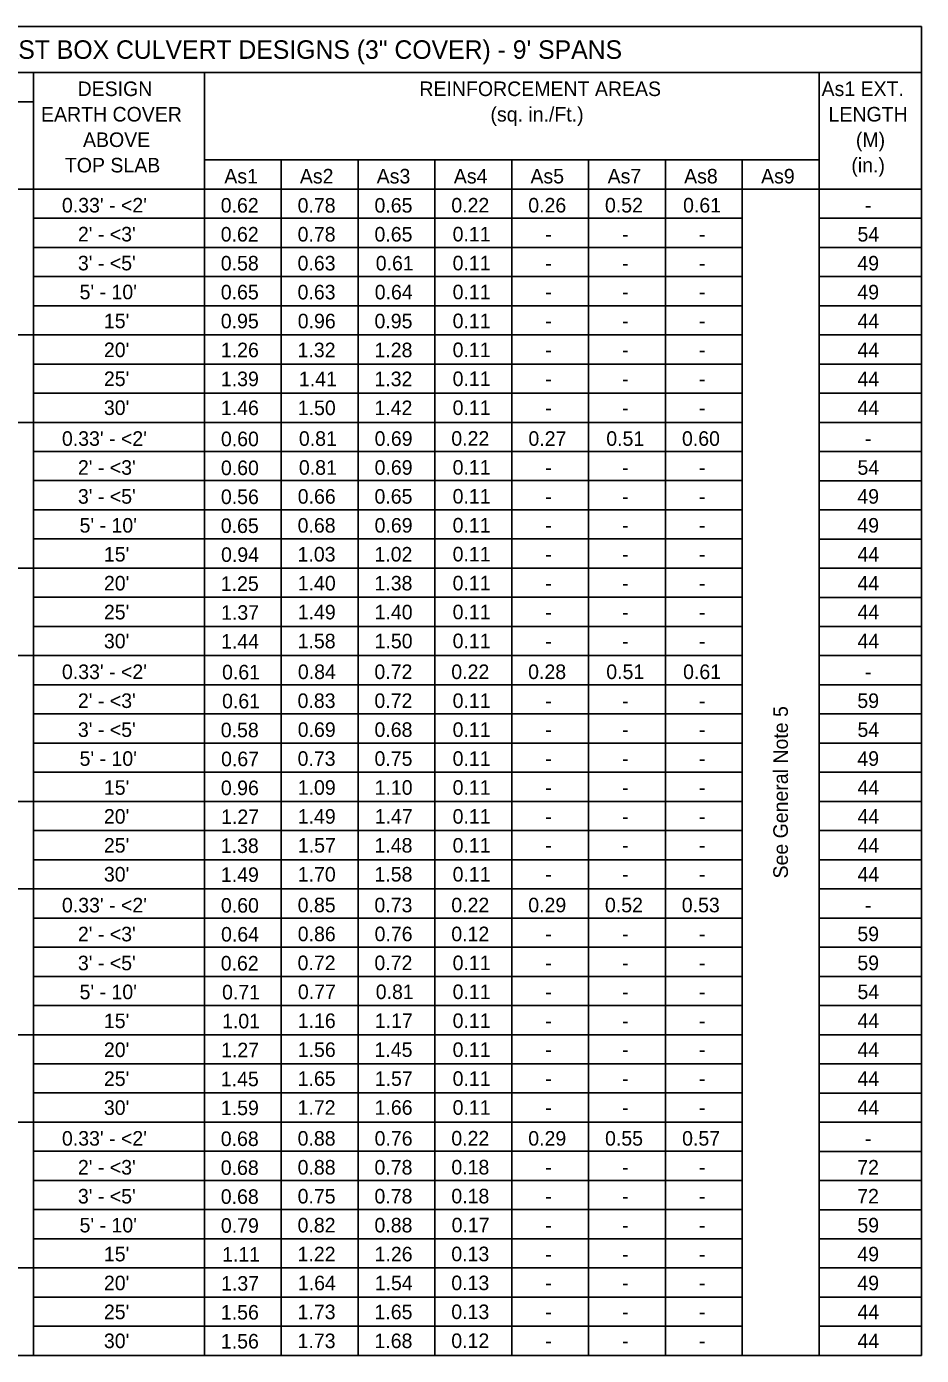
# Model space of a CAD drawing. Extents: x 10346.98 to 10349.19, y 76371.36 to 76372.62.
# Drawn here: x 10347.193 to 10347.579, y 76371.961 to 76372.535 of the extents above; entities that cross this region are included whole.
import ezdxf

# ---------------------------------------------------------------- set-up
doc = ezdxf.new("R2010")
doc.units = 0
doc.layers.add('AdhocPoint_dp', color=7, linetype='Continuous')
doc.layers.add('PlotBorder_dp', color=7, linetype='Continuous')

msp = doc.modelspace()

# ---------------------------------------------------------------- linework, layer by layer
at = {"layer": 'PlotBorder_dp'}
for p, q in [((10346.98451, 76372.53475), (10347.57925, 76372.53475)), ((10347.57925, 76372.53475), (10347.57925, 76371.96053)), ((10346.98451, 76372.51488), (10347.57925, 76372.51488)), ((10347.19559, 76372.51488), (10347.19559, 76371.96053)), ((10347.26947, 76372.51488), (10347.26947, 76371.96053)), ((10347.53506, 76372.51488), (10347.53506, 76371.96053)), ((10347.05314, 76372.50228), (10347.19559, 76372.50228)), ((10347.26947, 76372.47713), (10347.53506, 76372.47713)), ((10347.30267, 76372.47713), (10347.30267, 76371.96053)), ((10347.33586, 76372.47713), (10347.33586, 76371.96053)), ((10347.36906, 76372.47713), (10347.36906, 76371.96053)), ((10347.40226, 76372.47713), (10347.40226, 76371.96053)), ((10347.43546, 76372.47713), (10347.43546, 76371.96053)), ((10347.43546, 76372.47713), (10347.43546, 76371.96053)), ((10347.46866, 76372.47713), (10347.46866, 76371.96053)), ((10347.50186, 76372.47713), (10347.50186, 76371.96053)), ((10346.98451, 76372.46453), (10347.57925, 76372.46453)), ((10347.19559, 76372.45193), (10347.50186, 76372.45193)), ((10347.53506, 76372.45191), (10347.57925, 76372.45191)), ((10347.19559, 76372.43933), (10347.50186, 76372.43933)), ((10347.53506, 76372.43931), (10347.57925, 76372.43931)), ((10347.19559, 76372.42673), (10347.50186, 76372.42673)), ((10347.53506, 76372.42671), (10347.57925, 76372.42671)), ((10347.19559, 76372.41413), (10347.50186, 76372.41413)), ((10347.53506, 76372.41411), (10347.57925, 76372.41411)), ((10347.19559, 76372.40153), (10347.05314, 76372.40153)), ((10347.19559, 76372.40153), (10347.50186, 76372.40153)), ((10347.53506, 76372.40151), (10347.57925, 76372.40151)), ((10347.19559, 76372.38893), (10347.50186, 76372.38893)), ((10347.53506, 76372.38891), (10347.57925, 76372.38891)), ((10347.19559, 76372.37633), (10347.50186, 76372.37633)), ((10347.53506, 76372.37631), (10347.57925, 76372.37631)), ((10346.98451, 76372.36373), (10347.50186, 76372.36373)), ((10347.53506, 76372.36371), (10347.57925, 76372.36371)), ((10347.19559, 76372.35113), (10347.50186, 76372.35113)), ((10347.53506, 76372.35111), (10347.57925, 76372.35111)), ((10347.19559, 76372.33853), (10347.50186, 76372.33853)), ((10347.53506, 76372.33851), (10347.57925, 76372.33851)), ((10347.19559, 76372.32593), (10347.50186, 76372.32593)), ((10347.53506, 76372.32591), (10347.57925, 76372.32591)), ((10347.19559, 76372.31333), (10347.50186, 76372.31333)), ((10347.53506, 76372.31331), (10347.57925, 76372.31331)), ((10347.19559, 76372.30073), (10347.05314, 76372.30073)), ((10347.19559, 76372.30073), (10347.50186, 76372.30073)), ((10347.53506, 76372.30071), (10347.57925, 76372.30071)), ((10347.19559, 76372.28813), (10347.50186, 76372.28813)), ((10347.53506, 76372.28811), (10347.57925, 76372.28811)), ((10347.19559, 76372.27553), (10347.50186, 76372.27553)), ((10347.53506, 76372.27551), (10347.57925, 76372.27551)), ((10346.98451, 76372.26293), (10347.50186, 76372.26293)), ((10347.19621, 76372.26291), (10347.26838, 76372.26291)), ((10347.53506, 76372.26291), (10347.57925, 76372.26291)), ((10347.19559, 76372.25033), (10347.50186, 76372.25033)), ((10347.53506, 76372.25031), (10347.57925, 76372.25031)), ((10347.19559, 76372.23773), (10347.50186, 76372.23773)), ((10347.53506, 76372.23771), (10347.57925, 76372.23771)), ((10347.19559, 76372.22513), (10347.50186, 76372.22513)), ((10347.53506, 76372.22511), (10347.57925, 76372.22511)), ((10347.19559, 76372.21253), (10347.50186, 76372.21253)), ((10347.53506, 76372.21251), (10347.57925, 76372.21251)), ((10347.19559, 76372.19993), (10347.05314, 76372.19993)), ((10347.19559, 76372.19993), (10347.50186, 76372.19993)), ((10347.53506, 76372.19991), (10347.57925, 76372.19991)), ((10347.19559, 76372.18733), (10347.50186, 76372.18733)), ((10347.53506, 76372.18731), (10347.57925, 76372.18731)), ((10347.19559, 76372.17473), (10347.50186, 76372.17473)), ((10347.53506, 76372.17471), (10347.57925, 76372.17471)), ((10346.98451, 76372.16213), (10347.50186, 76372.16213)), ((10347.19621, 76372.16211), (10347.26838, 76372.16211)), ((10347.19621, 76372.16211), (10347.26838, 76372.16211)), ((10347.53506, 76372.16211), (10347.57925, 76372.16211)), ((10347.19559, 76372.14953), (10347.50186, 76372.14953)), ((10347.53506, 76372.14951), (10347.57925, 76372.14951)), ((10347.19559, 76372.13693), (10347.50186, 76372.13693)), ((10347.53506, 76372.13691), (10347.57925, 76372.13691)), ((10347.19559, 76372.12433), (10347.50186, 76372.12433)), ((10347.53506, 76372.12431), (10347.57925, 76372.12431)), ((10347.19559, 76372.11173), (10347.50186, 76372.11173)), ((10347.53506, 76372.11171), (10347.57925, 76372.11171)), ((10347.19559, 76372.09913), (10347.05314, 76372.09913)), ((10347.19559, 76372.09913), (10347.50186, 76372.09913)), ((10347.53506, 76372.09911), (10347.57925, 76372.09911)), ((10347.19559, 76372.08653), (10347.50186, 76372.08653)), ((10347.53506, 76372.08651), (10347.57925, 76372.08651)), ((10347.19559, 76372.07393), (10347.50186, 76372.07393)), ((10347.53506, 76372.07391), (10347.57925, 76372.07391)), ((10346.98451, 76372.06133), (10347.50186, 76372.06133)), ((10347.19621, 76372.06131), (10347.26838, 76372.06131)), ((10347.19621, 76372.06131), (10347.26838, 76372.06131)), ((10347.19621, 76372.06131), (10347.26838, 76372.06131)), ((10347.53506, 76372.06131), (10347.57925, 76372.06131)), ((10347.19559, 76372.04873), (10347.50186, 76372.04873)), ((10347.53506, 76372.04871), (10347.57925, 76372.04871)), ((10347.19559, 76372.03613), (10347.50186, 76372.03613)), ((10347.53506, 76372.03611), (10347.57925, 76372.03611)), ((10347.19559, 76372.02353), (10347.50186, 76372.02353)), ((10347.53506, 76372.02351), (10347.57925, 76372.02351)), ((10347.19559, 76372.01093), (10347.50186, 76372.01093)), ((10347.53506, 76372.01091), (10347.57925, 76372.01091)), ((10347.19559, 76371.99833), (10347.05314, 76371.99833)), ((10347.19559, 76371.99833), (10347.50186, 76371.99833)), ((10347.53506, 76371.99831), (10347.57925, 76371.99831)), ((10347.19559, 76371.98573), (10347.50186, 76371.98573)), ((10347.53506, 76371.98571), (10347.57925, 76371.98571)), ((10347.19559, 76371.97313), (10347.50186, 76371.97313)), ((10347.53506, 76371.97311), (10347.57925, 76371.97311)), ((10346.98451, 76371.96053), (10347.57925, 76371.96053))]:
    msp.add_line(p, q, dxfattribs=at)

# ---------------------------------------------------------------- texts
at = {"layer": 'AdhocPoint_dp'}
for s, height, p in [('TABLE 13A - STANDARD PRECAST BOX CULVERT DESIGNS (3" COVER) - 9\' SPANS', 0.008, (10347.02499, 76372.52081)), ('As1', 0.0063, (10347.27809, 76372.46696)), ('As2', 0.0063, (10347.31072, 76372.46696)), ('As3', 0.0063, (10347.34391, 76372.46696)), ('As4', 0.0063, (10347.37724, 76372.46696)), ('As5', 0.0063, (10347.41034, 76372.46696)), ('As7', 0.0063, (10347.44368, 76372.46696)), ('As8', 0.0063, (10347.47673, 76372.46696)), ('As9', 0.0063, (10347.50998, 76372.46696))]:
    msp.add_text(s, height=height, dxfattribs=at).set_placement(p)
msp.add_text('See General Note 5', height=0.0063, rotation=90, dxfattribs=at).set_placement((10347.52156, 76372.16663))
at = {"layer": 'PlotBorder_dp'}
for s, p in [('DESIGN', (10347.21469, 76372.50472)), ('REINFORCEMENT AREAS', (10347.36237, 76372.50472)), ('EARTH COVER', (10347.1989, 76372.49372)), ('(sq. in./Ft.)', (10347.39306, 76372.49372)), ('ABOVE', (10347.21704, 76372.48272)), ('TOP SLAB', (10347.20921, 76372.47172)), ("0.33' - <2'", (10347.20794, 76372.45441)), ('0.62', (10347.27654, 76372.45436)), ('0.78', (10347.30976, 76372.45436)), ('0.65', (10347.34297, 76372.45436)), ('0.22', (10347.37615, 76372.45441)), ('0.26', (10347.4094, 76372.45441)), ('0.52', (10347.44254, 76372.45441)), ('0.61', (10347.47629, 76372.45441)), ("2' - <3'", (10347.21484, 76372.44191)), ('0.62', (10347.27654, 76372.44186)), ('0.78', (10347.30976, 76372.44186)), ('0.65', (10347.34297, 76372.44186)), ('0.11', (10347.37672, 76372.44191)), ('-', (10347.41673, 76372.44191)), ('-', (10347.44994, 76372.44191)), ('-', (10347.48313, 76372.44191)), ("3' - <5'", (10347.21484, 76372.42941)), ('0.58', (10347.27656, 76372.42936)), ('0.63', (10347.30974, 76372.42936)), ('0.61', (10347.34351, 76372.42936)), ('0.11', (10347.37672, 76372.42941)), ('-', (10347.41673, 76372.42941)), ('-', (10347.44994, 76372.42941)), ('-', (10347.48313, 76372.42941)), ("5' - 10'", (10347.21556, 76372.41691)), ('0.65', (10347.27657, 76372.41686)), ('0.63', (10347.30974, 76372.41686)), ('0.64', (10347.34307, 76372.41686)), ('0.11', (10347.37672, 76372.41691)), ('-', (10347.41673, 76372.41691)), ('-', (10347.44994, 76372.41691)), ('-', (10347.48313, 76372.41691)), ("15'", (10347.22607, 76372.40441)), ('0.95', (10347.27657, 76372.40436)), ('0.96', (10347.30981, 76372.40436)), ('0.95', (10347.34297, 76372.40436)), ('0.11', (10347.37672, 76372.40441)), ('-', (10347.41673, 76372.40441)), ('-', (10347.44994, 76372.40441)), ('-', (10347.48313, 76372.40441)), ("20'", (10347.22607, 76372.39191)), ('1.26', (10347.27661, 76372.39186)), ('1.32', (10347.30974, 76372.39186)), ('1.28', (10347.34296, 76372.39186)), ('0.11', (10347.37672, 76372.39191)), ('-', (10347.41673, 76372.39191)), ('-', (10347.44994, 76372.39191)), ('-', (10347.48313, 76372.39191)), ("25'", (10347.22607, 76372.37941)), ('1.39', (10347.27661, 76372.37936)), ('1.41', (10347.31031, 76372.37936)), ('1.32', (10347.34294, 76372.37936)), ('0.11', (10347.37672, 76372.37941)), ('-', (10347.41673, 76372.37941)), ('-', (10347.44994, 76372.37941)), ('-', (10347.48313, 76372.37941)), ("30'", (10347.22607, 76372.36691)), ('1.46', (10347.27661, 76372.36686)), ('1.50', (10347.30982, 76372.36686)), ('1.42', (10347.34294, 76372.36686)), ('0.11', (10347.37672, 76372.36691)), ('-', (10347.41673, 76372.36691)), ('-', (10347.44994, 76372.36691)), ('-', (10347.48313, 76372.36691)), ("0.33' - <2'", (10347.20794, 76372.35358)), ('0.60', (10347.27662, 76372.35342)), ('0.81', (10347.31031, 76372.35358)), ('0.69', (10347.34301, 76372.35358)), ('0.22', (10347.37615, 76372.35363)), ('0.27', (10347.40947, 76372.35358)), ('0.51', (10347.44311, 76372.35358)), ('0.60', (10347.4758, 76372.35358)), ('-', (10347.55483, 76372.35358)), ("2' - <3'", (10347.21484, 76372.34108)), ('0.60', (10347.27662, 76372.34092)), ('0.81', (10347.31031, 76372.34108)), ('0.69', (10347.34301, 76372.34108)), ('0.11', (10347.37672, 76372.34113)), ('54', (10347.55163, 76372.34108)), ('-', (10347.41673, 76372.34108)), ('-', (10347.44994, 76372.34108)), ('-', (10347.48313, 76372.34108)), ("3' - <5'", (10347.21484, 76372.32858)), ('0.56', (10347.27661, 76372.32842)), ('0.66', (10347.30981, 76372.32858)), ('0.65', (10347.34297, 76372.32858)), ('0.11', (10347.37672, 76372.32863)), ('49', (10347.55157, 76372.32858)), ('-', (10347.41673, 76372.32858)), ('-', (10347.44994, 76372.32858)), ('-', (10347.48313, 76372.32858)), ("5' - 10'", (10347.21556, 76372.31608)), ('0.65', (10347.27657, 76372.31592)), ('0.68', (10347.30976, 76372.31608)), ('0.69', (10347.34301, 76372.31608)), ('0.11', (10347.37672, 76372.31613)), ('-', (10347.41673, 76372.31608)), ('-', (10347.44994, 76372.31608)), ('-', (10347.48313, 76372.31608)), ('49', (10347.55157, 76372.31608)), ("15'", (10347.22607, 76372.30358)), ('0.94', (10347.27667, 76372.30342)), ('1.03', (10347.30974, 76372.30358)), ('1.02', (10347.34294, 76372.30358)), ('0.11', (10347.37672, 76372.30363)), ('-', (10347.41673, 76372.30358)), ('-', (10347.44994, 76372.30358)), ('-', (10347.48313, 76372.30358)), ('44', (10347.55163, 76372.30358)), ("20'", (10347.22607, 76372.29108)), ('1.25', (10347.27657, 76372.29092)), ('1.40', (10347.30982, 76372.29108)), ('1.38', (10347.34296, 76372.29108)), ('0.11', (10347.37672, 76372.29113)), ('44', (10347.55163, 76372.29108)), ('-', (10347.41673, 76372.29108)), ('-', (10347.44994, 76372.29108)), ('-', (10347.48313, 76372.29108)), ("25'", (10347.22607, 76372.27858)), ('1.37', (10347.27669, 76372.27842)), ('1.49', (10347.30981, 76372.27858)), ('1.40', (10347.34302, 76372.27858)), ('0.11', (10347.37672, 76372.27863)), ('44', (10347.55163, 76372.27858)), ('-', (10347.41673, 76372.27858)), ('-', (10347.44994, 76372.27858)), ('-', (10347.48313, 76372.27858)), ("30'", (10347.22607, 76372.26608)), ('1.44', (10347.27667, 76372.26592)), ('1.58', (10347.30976, 76372.26608)), ('1.50', (10347.34302, 76372.26608)), ('0.11', (10347.37672, 76372.26613)), ('44', (10347.55163, 76372.26608)), ('-', (10347.41673, 76372.26608)), ('-', (10347.44994, 76372.26608)), ('-', (10347.48313, 76372.26608)), ("0.33' - <2'", (10347.20794, 76372.2528)), ('0.61', (10347.27711, 76372.25264)), ('0.84', (10347.30987, 76372.2528)), ('0.72', (10347.34294, 76372.2528)), ('0.22', (10347.37615, 76372.2528)), ('0.28', (10347.40935, 76372.2528)), ('0.51', (10347.44311, 76372.2528)), ('0.61', (10347.47629, 76372.2528)), ('-', (10347.55483, 76372.2528)), ("2' - <3'", (10347.21484, 76372.2403)), ('0.61', (10347.27711, 76372.24014)), ('0.83', (10347.30974, 76372.2403)), ('0.72', (10347.34294, 76372.2403)), ('0.11', (10347.37672, 76372.2403)), ('-', (10347.41673, 76372.2403)), ('-', (10347.44994, 76372.2403)), ('-', (10347.48313, 76372.2403)), ('59', (10347.55157, 76372.2403)), ("3' - <5'", (10347.21484, 76372.2278)), ('0.58', (10347.27656, 76372.22764)), ('0.69', (10347.30981, 76372.2278)), ('0.68', (10347.34296, 76372.2278)), ('0.11', (10347.37672, 76372.2278)), ('54', (10347.55163, 76372.2278)), ('-', (10347.41673, 76372.2278)), ('-', (10347.44994, 76372.2278)), ('-', (10347.48313, 76372.2278)), ("5' - 10'", (10347.21556, 76372.2153)), ('0.67', (10347.27669, 76372.21514)), ('0.73', (10347.30974, 76372.2153)), ('0.75', (10347.34297, 76372.2153)), ('0.11', (10347.37672, 76372.2153)), ('49', (10347.55157, 76372.2153)), ('-', (10347.41673, 76372.2153)), ('-', (10347.44994, 76372.2153)), ('-', (10347.48313, 76372.2153)), ("15'", (10347.22607, 76372.2028)), ('0.96', (10347.27661, 76372.20264)), ('1.09', (10347.30981, 76372.2028)), ('1.10', (10347.34302, 76372.2028)), ('0.11', (10347.37672, 76372.2028)), ('44', (10347.55163, 76372.2028)), ('-', (10347.41673, 76372.2028)), ('-', (10347.44994, 76372.2028)), ('-', (10347.48313, 76372.2028)), ("20'", (10347.22607, 76372.1903)), ('1.27', (10347.27669, 76372.19014)), ('1.49', (10347.30981, 76372.1903)), ('1.47', (10347.34308, 76372.1903)), ('0.11', (10347.37672, 76372.1903)), ('44', (10347.55163, 76372.1903)), ('-', (10347.41673, 76372.1903)), ('-', (10347.44994, 76372.1903)), ('-', (10347.48313, 76372.1903)), ("25'", (10347.22607, 76372.1778)), ('1.38', (10347.27656, 76372.17764)), ('1.57', (10347.30988, 76372.1778)), ('1.48', (10347.34296, 76372.1778)), ('0.11', (10347.37672, 76372.1778)), ('-', (10347.41673, 76372.1778)), ('-', (10347.44994, 76372.1778)), ('-', (10347.48313, 76372.1778)), ('44', (10347.55163, 76372.1778)), ("30'", (10347.22607, 76372.1653)), ('1.49', (10347.27661, 76372.16514)), ('1.70', (10347.30982, 76372.1653)), ('1.58', (10347.34296, 76372.1653)), ('0.11', (10347.37672, 76372.1653)), ('-', (10347.41673, 76372.1653)), ('-', (10347.44994, 76372.1653)), ('-', (10347.48313, 76372.1653)), ('44', (10347.55163, 76372.1653)), ("0.33' - <2'", (10347.20794, 76372.15196)), ('0.60', (10347.27662, 76372.15186)), ('0.85', (10347.30977, 76372.15201)), ('0.73', (10347.34294, 76372.15201)), ('0.22', (10347.37615, 76372.15201)), ('0.29', (10347.4094, 76372.15201)), ('0.52', (10347.44254, 76372.15201)), ('0.53', (10347.47572, 76372.15201)), ('-', (10347.55483, 76372.15201)), ("2' - <3'", (10347.21484, 76372.13946)), ('0.64', (10347.27667, 76372.13936)), ('0.86', (10347.30981, 76372.13951)), ('0.76', (10347.34301, 76372.13951)), ('0.12', (10347.37615, 76372.13951)), ('59', (10347.55157, 76372.13951)), ('-', (10347.41673, 76372.13951)), ('-', (10347.44994, 76372.13951)), ('-', (10347.48313, 76372.13951)), ("3' - <5'", (10347.21484, 76372.12696)), ('0.72', (10347.30974, 76372.12701)), ('0.72', (10347.34294, 76372.12701)), ('0.11', (10347.37672, 76372.12701)), ('59', (10347.55157, 76372.12701)), ('0.62', (10347.27654, 76372.12686)), ('-', (10347.41673, 76372.12701)), ('-', (10347.44994, 76372.12701)), ('-', (10347.48313, 76372.12701)), ("5' - 10'", (10347.21556, 76372.11446)), ('0.71', (10347.27711, 76372.11436)), ('0.77', (10347.30988, 76372.11451)), ('0.81', (10347.34351, 76372.11451)), ('0.11', (10347.37672, 76372.11451)), ('-', (10347.41673, 76372.11451)), ('-', (10347.44994, 76372.11451)), ('-', (10347.48313, 76372.11451)), ('54', (10347.55163, 76372.11451)), ("15'", (10347.22607, 76372.10196)), ('1.01', (10347.27711, 76372.10186)), ('1.16', (10347.30981, 76372.10201)), ('1.17', (10347.34308, 76372.10201)), ('0.11', (10347.37672, 76372.10201)), ('-', (10347.41673, 76372.10201)), ('-', (10347.44994, 76372.10201)), ('-', (10347.48313, 76372.10201)), ('44', (10347.55163, 76372.10201)), ("20'", (10347.22607, 76372.08946)), ('1.27', (10347.27669, 76372.08936)), ('1.56', (10347.30981, 76372.08951)), ('1.45', (10347.34297, 76372.08951)), ('0.11', (10347.37672, 76372.08951)), ('44', (10347.55163, 76372.08951)), ('-', (10347.41673, 76372.08951)), ('-', (10347.44994, 76372.08951)), ('-', (10347.48313, 76372.08951)), ("25'", (10347.22607, 76372.07696)), ('1.45', (10347.27657, 76372.07686)), ('1.65', (10347.30977, 76372.07701)), ('1.57', (10347.34308, 76372.07701)), ('0.11', (10347.37672, 76372.07701)), ('44', (10347.55163, 76372.07701)), ('-', (10347.41673, 76372.07701)), ('-', (10347.44994, 76372.07701)), ('-', (10347.48313, 76372.07701)), ("30'", (10347.22607, 76372.06446)), ('1.59', (10347.27661, 76372.06436)), ('1.72', (10347.30974, 76372.06451)), ('1.66', (10347.34301, 76372.06451)), ('0.11', (10347.37672, 76372.06451)), ('44', (10347.55163, 76372.06451)), ('-', (10347.41673, 76372.06451)), ('-', (10347.44994, 76372.06451)), ('-', (10347.48313, 76372.06451)), ("0.33' - <2'", (10347.20794, 76372.05118)), ('0.68', (10347.27656, 76372.05102)), ('0.88', (10347.30976, 76372.05118)), ('0.76', (10347.34301, 76372.05118)), ('0.22', (10347.37615, 76372.05123)), ('0.29', (10347.4094, 76372.05118)), ('0.55', (10347.44257, 76372.05118)), ('0.57', (10347.47587, 76372.05118)), ('-', (10347.55483, 76372.05118)), ("2' - <3'", (10347.21484, 76372.03868)), ('0.68', (10347.27656, 76372.03852)), ('0.88', (10347.30976, 76372.03868)), ('0.78', (10347.34296, 76372.03868)), ('0.18', (10347.37617, 76372.03873)), ('72', (10347.5515, 76372.03868)), ('-', (10347.41673, 76372.03868)), ('-', (10347.44994, 76372.03868)), ('-', (10347.48313, 76372.03868)), ("3' - <5'", (10347.21484, 76372.02618)), ('0.68', (10347.27656, 76372.02602)), ('0.75', (10347.30977, 76372.02618)), ('0.78', (10347.34296, 76372.02618)), ('0.18', (10347.37617, 76372.02623)), ('72', (10347.5515, 76372.02618)), ('-', (10347.41673, 76372.02618)), ('-', (10347.44994, 76372.02618)), ('-', (10347.48313, 76372.02618)), ("5' - 10'", (10347.21556, 76372.01368)), ('0.79', (10347.27661, 76372.01352)), ('0.82', (10347.30974, 76372.01368)), ('0.88', (10347.34296, 76372.01368)), ('0.17', (10347.37629, 76372.01373)), ('59', (10347.55157, 76372.01368)), ('-', (10347.41673, 76372.01368)), ('-', (10347.44994, 76372.01368)), ('-', (10347.48313, 76372.01368)), ("15'", (10347.22607, 76372.00118)), ('1.11', (10347.27711, 76372.00102)), ('1.22', (10347.30974, 76372.00118)), ('1.26', (10347.34301, 76372.00118)), ('0.13', (10347.37615, 76372.00123)), ('49', (10347.55157, 76372.00118)), ('-', (10347.41673, 76372.00118)), ('-', (10347.44994, 76372.00118)), ('-', (10347.48313, 76372.00118)), ("20'", (10347.22607, 76371.98868)), ('1.37', (10347.27669, 76371.98852)), ('1.64', (10347.30987, 76371.98868)), ('1.54', (10347.34307, 76371.98868)), ('0.13', (10347.37615, 76371.98873)), ('-', (10347.41673, 76371.98868)), ('-', (10347.44994, 76371.98868)), ('-', (10347.48313, 76371.98868)), ('49', (10347.55157, 76371.98868)), ("25'", (10347.22607, 76371.97618)), ('1.56', (10347.27661, 76371.97602)), ('1.73', (10347.30974, 76371.97618)), ('1.65', (10347.34297, 76371.97618)), ('0.13', (10347.37615, 76371.97623)), ('-', (10347.41673, 76371.97618)), ('-', (10347.44994, 76371.97618)), ('-', (10347.48313, 76371.97618)), ('44', (10347.55163, 76371.97618)), ("30'", (10347.22607, 76371.96368)), ('1.56', (10347.27661, 76371.96352)), ('1.73', (10347.30974, 76371.96368)), ('1.68', (10347.34296, 76371.96368)), ('0.12', (10347.37615, 76371.96373)), ('44', (10347.55163, 76371.96368)), ('-', (10347.41673, 76371.96368)), ('-', (10347.44994, 76371.96368)), ('-', (10347.48313, 76371.96368))]:
    msp.add_text(s, height=0.0063, dxfattribs=at).set_placement(p)
for s, p in [('As1 EXT.', (10347.5361, 76372.50472)), ('LENGTH', (10347.53913, 76372.49372)), ('(M)', (10347.55093, 76372.48272)), ('(in.)', (10347.54897, 76372.47172)), ('-', (10347.55483, 76372.45436)), ('54', (10347.55163, 76372.44186)), ('49', (10347.55157, 76372.42936)), ('49', (10347.55157, 76372.41686)), ('44', (10347.55163, 76372.40436)), ('44', (10347.55163, 76372.39186)), ('44', (10347.55163, 76372.37936)), ('44', (10347.55163, 76372.36686))]:
    msp.add_text(s, height=0.0063, rotation=360, dxfattribs=at).set_placement(p)

doc.saveas('drawing.dxf')
